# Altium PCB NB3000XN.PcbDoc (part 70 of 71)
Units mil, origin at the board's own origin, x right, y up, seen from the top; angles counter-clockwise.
Board outline 9527.56 x 6929.77 mil, 6 copper layers (Top Layer, GND+SHIELD, MidLayer1, MidLayer2, P2 - 3V3+5V0, Bottom Layer), stack 62.375 mil thick; 832 components, 1027 nets, 4655 pads, 4981 vias.
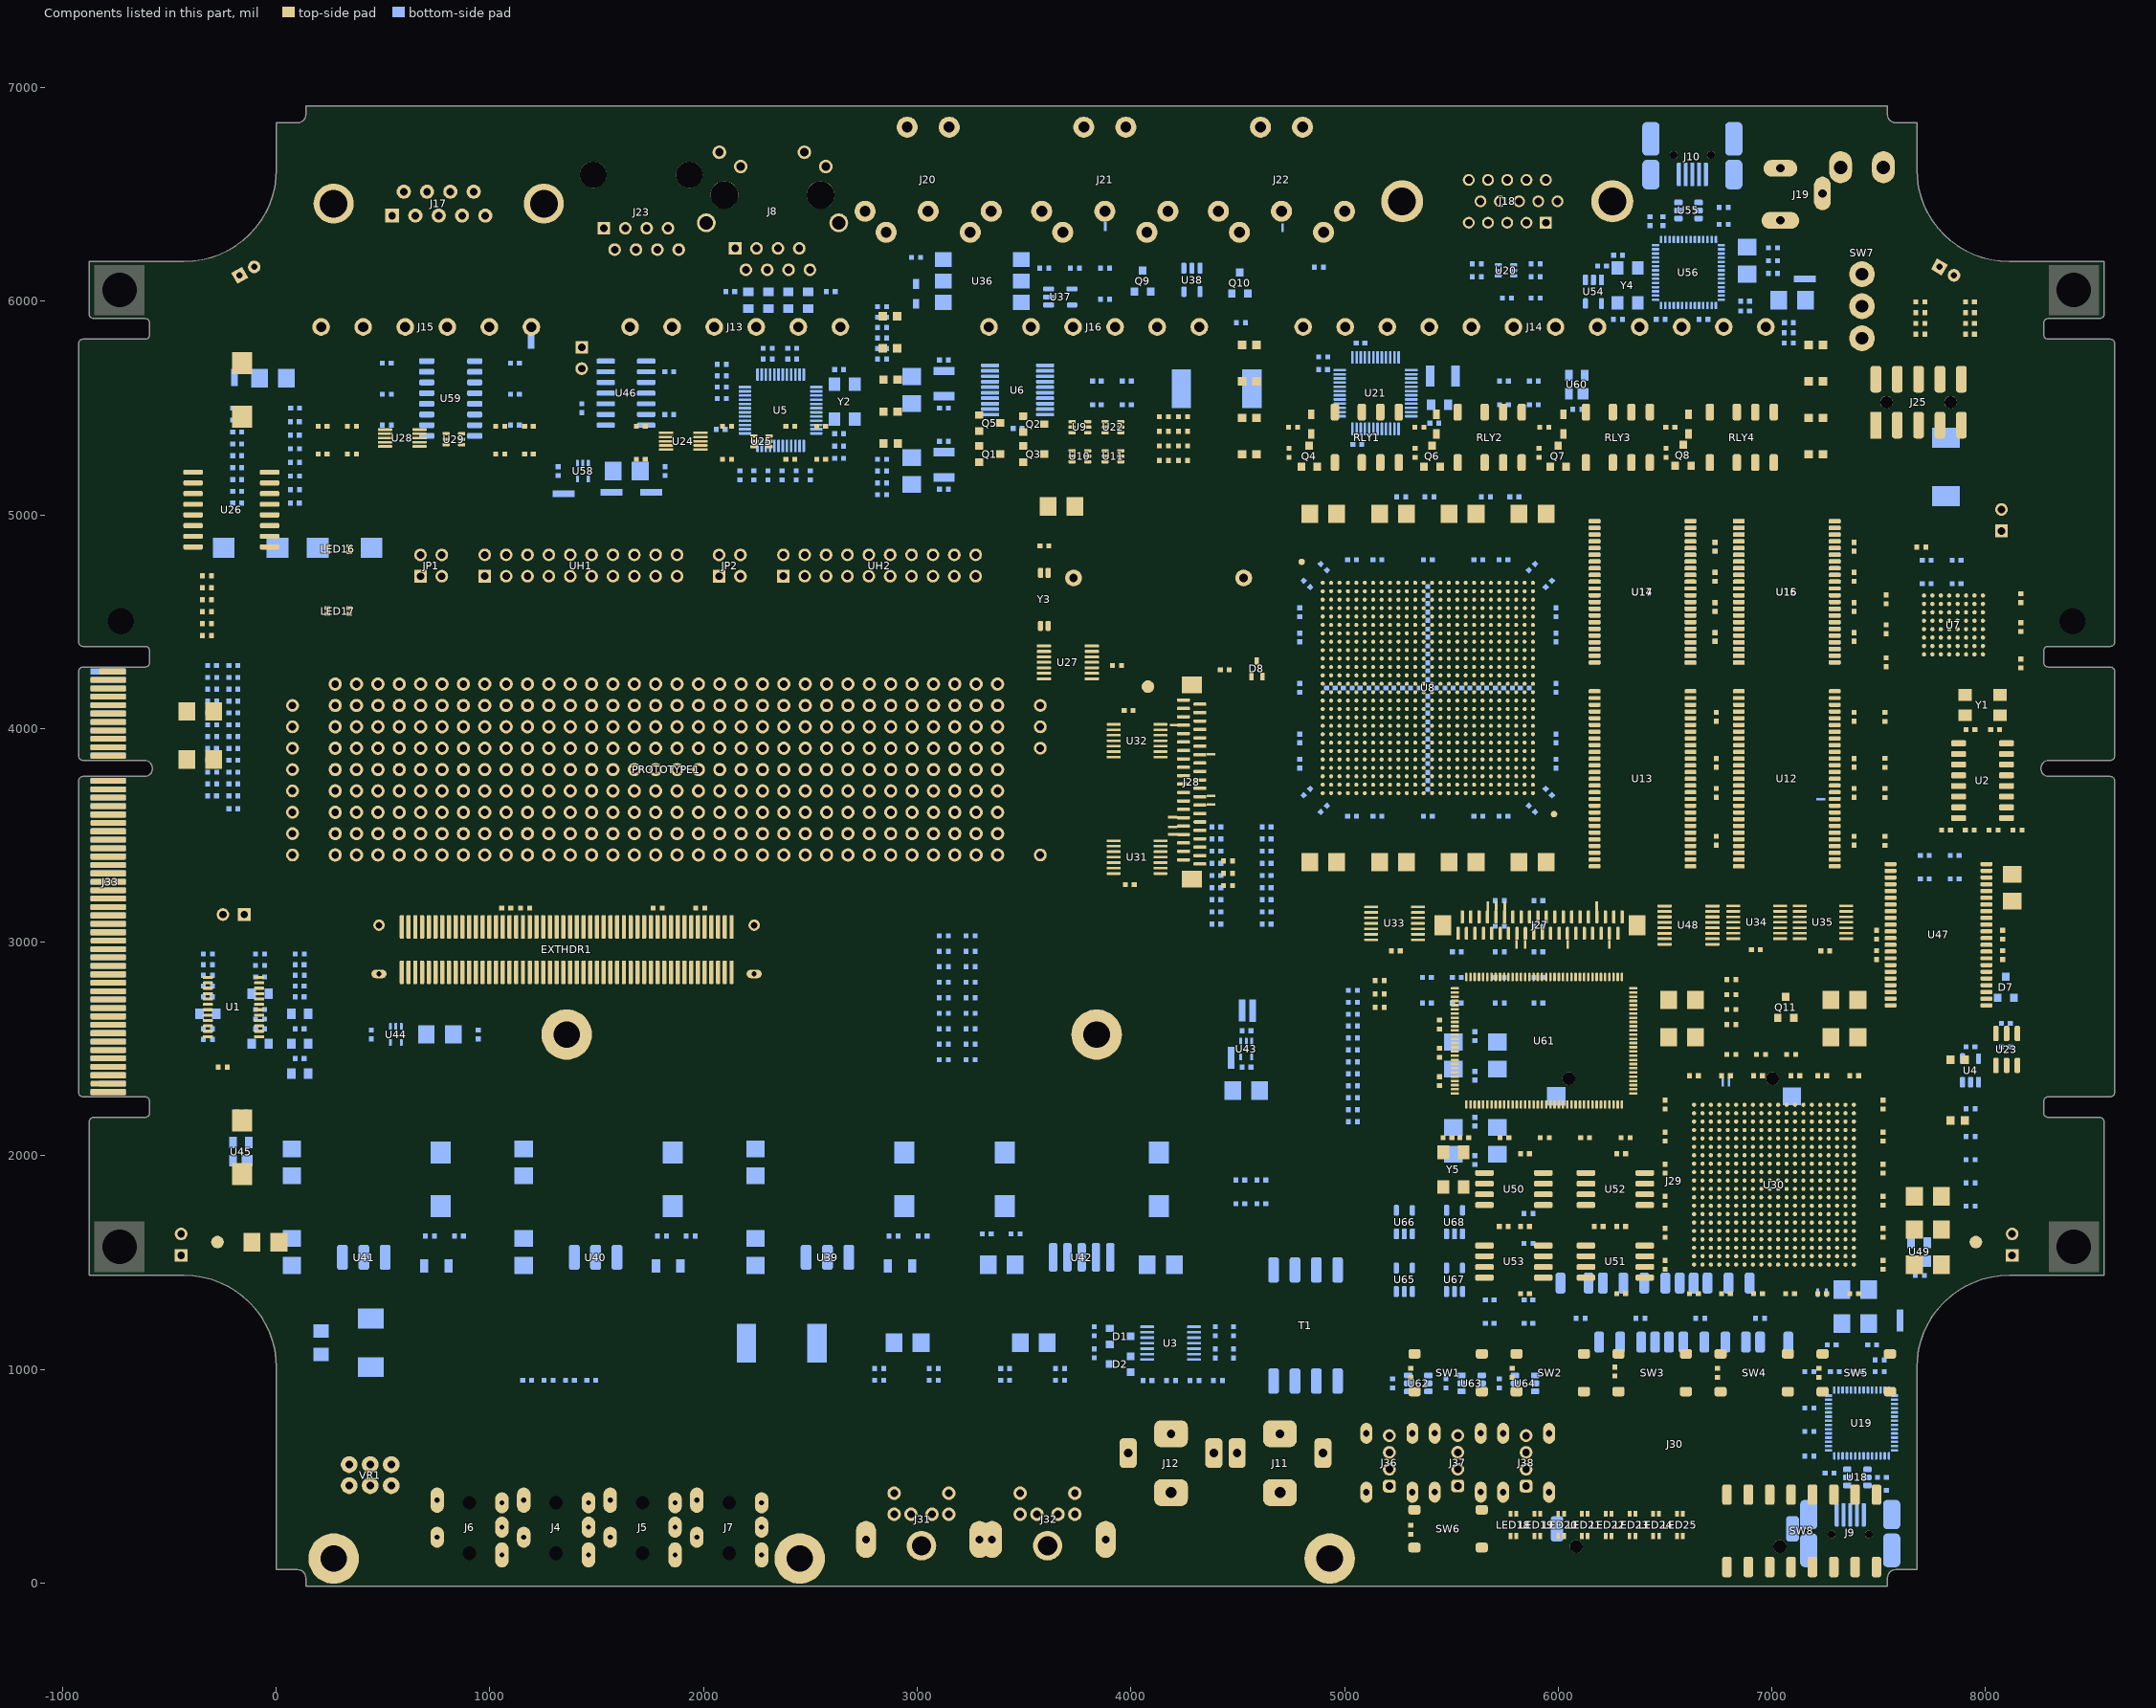
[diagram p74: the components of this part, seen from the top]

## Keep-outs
Keep-Out Layer:
  lines w15: -923.8,2295.89 -923.31,2291.51 -921.85,2287.35 -919.5,2283.62 -916.39,2280.5 -912.66,2278.15 -908.49,2276.7 -904.11,2276.2 -612.78,2276.2 -608.4,2275.71 -604.24,2274.25 -600.5,2271.91 -597.39,2268.79 -595.04,2265.06 -593.59,2260.9 -593.09,2256.52 -593.09,2199.42 -593.59,2195.04 -595.04,2190.88 -597.39,2187.15 -600.5,2184.03 -604.24,2181.68 -608.4,2180.23 -612.78,2179.74 -854.9,2179.74 -859.28,2179.24 -863.44,2177.79 -867.17,2175.44 -870.29,2172.32 -872.64,2168.59 -874.09,2164.43 -874.59,2160.05 -874.59,1441.32 -431.67,1441.32 -389.22,1439.23 -347.19,1433 -305.96,1422.67 -265.94,1408.35 -227.52,1390.18 -191.07,1368.33 -156.94,1343.01 -125.45,1314.46 -96.9,1282.97 -71.59,1248.83 -49.74,1212.37 -31.57,1173.95 -17.25,1133.93 -6.92,1092.7 -0.69,1050.65 1.4,1008.2 1.4,63.2 99.82,63.2 108.58,62.22 116.9,59.3 124.37,54.61 130.6,48.38 135.29,40.91 138.21,32.59 139.19,23.83 139.19,-15.55 7540.77,-15.55 7540.77,23.83 7541.76,32.59 7544.67,40.91 7549.36,48.38 7555.59,54.61 7563.06,59.31 7571.38,62.22 7580.14,63.2 7678.56,63.2 7678.56,1008.2 7680.65,1050.65 7686.89,1092.7 7697.21,1133.93 7711.53,1173.95 7729.7,1212.37 7751.55,1248.83 7776.87,1282.97 7805.41,1314.46 7836.9,1343.01 7871.03,1368.33 7907.49,1390.18 7945.91,1408.35 7985.92,1422.67 8027.15,1433 8069.19,1439.23 8111.63,1441.32 8554.55,1441.32 8554.55,2160.05 8554.05,2164.43 8552.6,2168.59 8550.25,2172.32 8547.13,2175.44 8543.4,2177.79 8539.24,2179.24 8534.86,2179.74 8292.74,2179.74 8288.36,2180.23 8284.2,2181.68 8280.47,2184.03 8277.35,2187.15 8275,2190.88 8273.55,2195.04 8273.05,2199.42 8273.05,2256.52 8273.55,2260.9 8275,2265.06 8277.35,2268.79 8280.47,2271.91 8284.2,2274.25 8288.36,2275.71 8292.74,2276.2 8584.08,2276.2 8588.46,2276.7 8592.62,2278.15 8596.35,2280.5 8599.46,2283.62 8601.81,2287.35 8603.27,2291.51 8603.76,2295.89 8603.76,3756.1 8603.27,3760.48 8601.81,3764.64 8599.46,3768.38 8596.35,3771.5 8592.62,3773.84 8588.46,3775.3 8584.08,3775.79 8296.67,3775.79 8288.9,3776.61 8281.46,3779.03 8274.69,3782.93 8268.88,3788.17 8264.28,3794.49 8261.1,3801.64 8259.48,3809.29 8259.48,3817.11 8261.1,3824.76 8264.28,3831.9 8268.88,3838.23 8274.69,3843.46 8281.46,3847.37 8288.9,3849.79 8296.67,3850.6 8584.08,3850.6 8588.46,3851.1 8592.62,3852.55 8596.35,3854.9 8599.46,3858.02 8601.81,3861.75 8603.27,3865.91 8603.76,3870.29 8603.76,4268.57 8603.27,4272.95 8601.81,4277.11 8599.46,4280.84 8596.35,4283.96 8592.62,4286.3 8588.46,4287.76 8584.08,4288.25 8292.74,4288.25 8288.36,4288.75 8284.2,4290.2 8280.47,4292.55 8277.35,4295.67 8275,4299.4 8273.55,4303.56 8273.05,4307.94 8273.05,4365.03 8273.55,4369.41 8275,4373.58 8277.35,4377.31 8280.47,4380.43 8284.2,4382.77 8288.36,4384.23 8292.74,4384.72 8584.08,4384.72 8588.46,4385.21 8592.62,4386.67 8596.35,4389.02 8599.46,4392.13 8601.81,4395.87 8603.27,4400.03 8603.76,4404.41 8603.76,5803 8603.27,5807.38 8601.81,5811.54 8599.46,5815.28 8596.35,5818.39 8592.62,5820.74 8588.46,5822.19 8584.08,5822.69 8292.74,5822.69 8288.36,5823.18 8284.2,5824.64 8280.47,5826.98 8277.35,5830.1 8275,5833.83 8273.55,5837.99 8273.05,5842.37 8273.05,5899.47 8273.55,5903.85 8275,5908.01 8277.35,5911.74 8280.47,5914.86 8284.2,5917.2 8288.36,5918.66 8292.74,5919.16 8534.86,5919.16 8539.24,5919.65 8543.4,5921.1 8547.13,5923.45 8550.25,5926.57 8552.6,5930.3 8554.05,5934.46 8554.55,5938.84 8554.55,6185.98 8110.73,6185.98 8068.37,6188.06 8026.42,6194.28 7985.28,6204.59 7945.35,6218.88 7907.01,6237.01 7870.63,6258.82 7836.57,6284.09 7805.14,6312.57 7776.66,6344 7751.4,6378.07 7729.59,6414.45 7711.46,6452.79 7697.17,6492.73 7686.87,6533.88 7680.65,6575.83 7678.56,6618.2 7678.56,6835.48 7580.14,6835.48 7571.38,6836.46 7563.05,6839.37 7555.59,6844.07 7549.36,6850.3 7544.67,6857.77 7541.76,6866.09 7540.77,6874.85 7540.77,6914.22 139.19,6914.22 139.19,6874.85 138.21,6866.09 135.29,6857.76 130.6,6850.3 124.37,6844.06 116.9,6839.37 108.58,6836.46 99.82,6835.47 1.4,6835.47 1.4,6618.2 -0.68,6575.83 -6.91,6533.87 -17.21,6492.73 -31.5,6452.79 -49.63,6414.45 -71.43,6378.07 -96.7,6344 -125.18,6312.57 -156.61,6284.09 -190.67,6258.82 -227.05,6237.01 -265.39,6218.88 -305.32,6204.59 -346.46,6194.28 -388.41,6188.06 -430.77,6185.98 -874.59,6185.98 -874.59,5938.84 -874.09,5934.46 -872.64,5930.3 -870.29,5926.57 -867.17,5923.45 -863.44,5921.1 -859.28,5919.65 -854.9,5919.15 -612.78,5919.15 -608.4,5918.66 -604.24,5917.2 -600.5,5914.86 -597.39,5911.74 -595.04,5908.01 -593.59,5903.85 -593.09,5899.47 -593.09,5842.37 -593.59,5837.99 -595.04,5833.83 -597.39,5830.1 -600.5,5826.98 -604.24,5824.64 -608.4,5823.18 -612.78,5822.69 -904.11,5822.69 -908.49,5822.19 -912.66,5820.74 -916.39,5818.39 -919.5,5815.27 -921.85,5811.54 -923.31,5807.38 -923.8,5803 -923.8,4404.41 -923.31,4400.03 -921.85,4395.87 -919.5,4392.13 -916.39,4389.02 -912.66,4386.67 -908.49,4385.21 -904.11,4384.72 -612.78,4384.72 -608.4,4384.23 -604.24,4382.77 -600.5,4380.43 -597.39,4377.31 -595.04,4373.58 -593.59,4369.41 -593.09,4365.03 -593.09,4307.94 -593.59,4303.56 -595.04,4299.4 -597.39,4295.67 -600.5,4292.55 -604.24,4290.2 -608.4,4288.75 -612.78,4288.25 -904.11,4288.25 -908.49,4287.76 -912.66,4286.3 -916.39,4283.96 -919.5,4280.84 -921.85,4277.11 -923.31,4272.95 -923.8,4268.56 -923.8,3870.29 -923.31,3865.91 -921.85,3861.75 -919.5,3858.01 -916.39,3854.9 -912.66,3852.55 -908.49,3851.1 -904.11,3850.6 -616.71,3850.6 -608.94,3849.79 -601.5,3847.37 -594.73,3843.46 -588.92,3838.23 -584.32,3831.9 -581.14,3824.76 -579.52,3817.11 -579.52,3809.29 -581.14,3801.64 -584.32,3794.49 -588.92,3788.17 -594.73,3782.93 -601.5,3779.02 -608.94,3776.61 -616.71,3775.79 -904.11,3775.79 -908.49,3775.3 -912.66,3773.84 -916.39,3771.49 -919.5,3768.38 -921.85,3764.64 -923.31,3760.48 -923.8,3756.1 -923.8,2295.89 ; -530.1,1864.15 -530.1,2218.52 -529.11,2227.28 -526.2,2235.6 -521.51,2243.07 -515.27,2249.3 -507.81,2253.99 -499.49,2256.91 -490.73,2257.89 -392.3,2257.89 -383.54,2256.91 -375.22,2253.99 -367.76,2249.3 -361.52,2243.07 -356.83,2235.6 -353.92,2227.28 -352.93,2218.52 -352.93,1864.15 -353.92,1855.38 -356.83,1847.06 -361.52,1839.6 -367.76,1833.36 -375.22,1828.67 -383.54,1825.76 -392.3,1824.77 -490.73,1824.77 -499.49,1825.76 -507.81,1828.67 -515.27,1833.36 -521.51,1839.6 -526.2,1847.06 -529.11,1855.38 -530.1,1864.15 ; -530.1,5407.88 -529.11,5399.11 -526.2,5390.79 -521.51,5383.32 -515.27,5377.09 -507.81,5372.4 -499.49,5369.49 -490.73,5368.5 -392.3,5368.5 -383.54,5369.49 -375.22,5372.4 -367.76,5377.09 -361.52,5383.32 -356.83,5390.79 -353.92,5399.11 -352.93,5407.88 -352.93,5762.25 -353.92,5771.01 -356.83,5779.33 -361.52,5786.8 -367.76,5793.03 -375.22,5797.72 -383.54,5800.64 -392.3,5801.62 -490.73,5801.62 -499.49,5800.64 -507.81,5797.72 -515.27,5793.03 -521.51,5786.8 -526.2,5779.33 -529.11,5771.01 -530.1,5762.25 -530.1,5407.88 ; 3623.45,3616.32 3624.43,3607.56 3627.34,3599.24 3632.03,3591.77 3638.27,3585.54 3645.73,3580.85 3654.05,3577.94 3662.81,3576.95 4017.15,3576.95 4025.91,3577.94 4034.23,3580.85 4041.69,3585.54 4047.93,3591.77 4052.62,3599.24 4055.53,3607.56 4056.52,3616.32 4056.52,3714.76 4055.53,3723.52 4052.62,3731.84 4047.93,3739.31 4041.69,3745.54 4034.23,3750.24 4025.91,3753.15 4017.15,3754.13 3662.81,3754.13 3654.05,3753.15 3645.73,3750.24 3638.27,3745.54 3632.03,3739.31 3627.34,3731.84 3624.43,3723.52 3623.45,3714.76 3623.45,3616.32 ; 4505.53,3715.21 4506.03,3710.83 4507.48,3706.67 4509.83,3702.94 4512.95,3699.82 4516.68,3697.47 4520.84,3696.02 4525.22,3695.52 4631.52,3695.52 4635.9,3696.02 4640.06,3697.47 4643.79,3699.82 4646.91,3702.94 4649.25,3706.67 4650.71,3710.83 4651.21,3715.21 4651.21,3912.08 4650.71,3916.47 4649.25,3920.63 4646.91,3924.36 4643.79,3927.48 4640.06,3929.82 4635.9,3931.28 4631.52,3931.77 4525.22,3931.77 4520.84,3931.28 4516.68,3929.82 4512.95,3927.48 4509.83,3924.36 4507.48,3920.63 4506.03,3916.47 4505.53,3912.08 4505.53,3715.21 ; 5224.07,2182.81 5224.57,2178.43 5226.02,2174.27 5228.37,2170.54 5231.48,2167.42 5235.21,2165.08 5239.37,2163.62 5243.76,2163.13 5350.06,2163.13 5354.43,2163.62 5358.6,2165.08 5362.33,2167.42 5365.45,2170.54 5367.79,2174.27 5369.25,2178.43 5369.74,2182.81 5369.74,2379.69 5369.25,2384.07 5367.79,2388.23 5365.45,2391.96 5362.33,2395.08 5358.6,2397.42 5354.43,2398.88 5350.06,2399.37 5243.76,2399.37 5239.37,2398.88 5235.21,2397.42 5231.48,2395.08 5228.37,2391.96 5226.02,2388.23 5224.57,2384.07 5224.07,2379.69 5224.07,2182.81 ; 7581.87,2182.81 7582.37,2178.43 7583.83,2174.27 7586.17,2170.54 7589.29,2167.42 7593.02,2165.08 7597.18,2163.62 7601.56,2163.13 7707.86,2163.13 7712.24,2163.62 7716.4,2165.08 7720.13,2167.42 7723.25,2170.54 7725.6,2174.27 7727.05,2178.43 7727.54,2182.81 7727.54,2379.69 7727.05,2384.07 7725.6,2388.23 7723.25,2391.96 7720.13,2395.08 7716.4,2397.42 7712.24,2398.88 7707.86,2399.37 7601.56,2399.37 7597.18,2398.88 7593.02,2397.42 7589.29,2395.08 7586.17,2391.96 7583.83,2388.23 7582.37,2384.07 7581.87,2379.69 7581.87,2182.81 ; 7603.95,3715.21 7604.45,3710.83 7605.9,3706.67 7608.25,3702.94 7611.37,3699.82 7615.1,3697.47 7619.26,3696.02 7623.64,3695.52 7729.94,3695.52 7734.32,3696.02 7738.48,3697.47 7742.21,3699.82 7745.33,3702.94 7747.67,3706.67 7749.13,3710.83 7749.62,3715.21 7749.62,3912.08 7749.13,3916.47 7747.67,3920.63 7745.33,3924.36 7742.21,3927.48 7738.48,3929.82 7734.32,3931.28 7729.94,3931.77 7623.64,3931.77 7619.26,3931.28 7615.1,3929.82 7611.37,3927.48 7608.25,3924.36 7605.9,3920.63 7604.45,3916.47 7603.95,3912.08 7603.95,3715.21 ; 8032.89,1864.15 8033.88,1855.39 8036.79,1847.06 8041.48,1839.6 8047.72,1833.36 8055.18,1828.67 8063.5,1825.76 8072.26,1824.77 8170.69,1824.77 8179.45,1825.76 8187.77,1828.67 8195.24,1833.36 8201.47,1839.6 8206.16,1847.06 8209.07,1855.39 8210.06,1864.15 8210.06,2218.52 8209.07,2227.28 8206.16,2235.6 8201.47,2243.07 8195.24,2249.3 8187.77,2254 8179.45,2256.91 8170.69,2257.89 8072.26,2257.89 8063.5,2256.91 8055.18,2254 8047.72,2249.3 8041.48,2243.07 8036.79,2235.6 8033.88,2227.28 8032.89,2218.52 8032.89,1864.15 ; 8032.89,5407.88 8033.88,5399.11 8036.79,5390.79 8041.48,5383.32 8047.72,5377.09 8055.18,5372.4 8063.5,5369.49 8072.26,5368.5 8170.69,5368.5 8179.45,5369.49 8187.77,5372.4 8195.24,5377.09 8201.47,5383.32 8206.16,5390.79 8209.07,5399.11 8210.06,5407.88 8210.06,5762.25 8209.07,5771.01 8206.16,5779.33 8201.47,5786.8 8195.24,5793.03 8187.77,5797.72 8179.45,5800.64 8170.69,5801.62 8072.26,5801.62 8063.5,5800.64 8055.18,5797.72 8047.72,5793.03 8041.48,5786.8 8036.79,5779.33 8033.88,5771.01 8032.89,5762.25 8032.89,5407.88

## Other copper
Top Layer:
  rectangle net GND: 3455,5210 3535,5285
  region net 2V5: 4114.02,1421.93 4114.02,1456.93 4039.02,1456.93 4039.02,1421.93
  region net 2V5: 4114.02,1525.79 4114.02,1560.79 4039.02,1560.79 4039.02,1525.79
  region net 2V5: 4167.01,1686.77 4167.01,1721.77 4092.01,1721.77 4092.01,1686.77
  region net 2V5: 4167.01,1808.82 4167.01,1843.82 4092.01,1843.82 4092.01,1808.82
  rectangle net GND: 3455,5350 3535,5439
  rectangle net GND: 3250,5355 3330,5430
  rectangle net GND: 3250,5210 3330,5285
  rectangle net GND: 115,4495 185,4525
  rectangle net 5V0: 5,1450 40,1525
  rectangle net 5V0: 108.86,1450 143.86,1525
  rectangle net GND: 108.86,1575.98 143.86,1650.98
  rectangle net 5V0: 258.86,1475 293.86,1585
  rectangle net 3V3: 428.86,1475 463.86,1670
  rectangle net 3V3: 454.85,1590 485,1670
  rectangle net GND: 5,1995 145,2070
  rectangle net 3V3: 5,1869.02 145,1944.02
  rectangle net 2V5: 1090,1868.03 1230,1943.03
  rectangle net GND: 1090,1994.02 1230,2069.02
  rectangle net 1V8: 2175,1868.03 2315,1943.03
  rectangle net GND: 2175,1994.02 2315,2069.02
  rectangle net 2V5: 1539.85,1590 1570,1670
  rectangle net 2V5: 1513.86,1475 1548.86,1670
  rectangle net 5V0: 1343.86,1475 1378.86,1585
  rectangle net 1V8: 2624.85,1590 2655,1670
  rectangle net 1V8: 2598.86,1475 2633.86,1670
  rectangle net 3V3: 2428.86,1475 2463.86,1585
  rectangle net GND: 2175,1574.02 2315,1649.02
  rectangle net 3V3: 2175,1448.03 2315,1523.03
  rectangle net 5V0: 648.86,1447.5 683.86,1522.5
  rectangle net 5V0: 704.68,1447.5 739.68,1522.5
  rectangle net GND: 763.03,1447.5 798.03,1522.5
  rectangle net GND: 818.86,1447.5 853.86,1522.5
  rectangle net GND: 1090,1575.98 1125,1650.98
  rectangle net 5V0: 1090,1450 1125,1525
  rectangle net GND: 1193.86,1575.98 1228.86,1650.98
  rectangle net 5V0: 1193.86,1450 1228.86,1525
  region net GND: 807.01,2060.79 807.01,2095.79 732.01,2095.79 732.01,2060.79
  region net GND: 807.01,1938.74 807.01,1973.74 732.01,1973.74 732.01,1938.74
  region net 3V3: 807.01,1808.82 807.01,1843.82 732.01,1843.82 732.01,1808.82
  region net 3V3: 807.01,1686.77 807.01,1721.77 732.01,1721.77 732.01,1686.77
  region net GND: 1892.01,2060.79 1892.01,2095.79 1817.01,2095.79 1817.01,2060.79
  region net GND: 1892.01,1938.74 1892.01,1973.74 1817.01,1973.74 1817.01,1938.74
  region net 2V5: 1862.01,1808.82 1862.01,1843.82 1787.01,1843.82 1787.01,1808.82
  region net 2V5: 1862.01,1686.77 1862.01,1721.77 1787.01,1721.77 1787.01,1686.77
  rectangle net 5V0: 1733.86,1447.5 1768.86,1522.5
  rectangle net 5V0: 1789.68,1447.5 1824.68,1522.5
  rectangle net GND: 1848.03,1447.5 1883.03,1522.5
  rectangle net GND: 1903.86,1447.5 1938.86,1522.5
  region net GND: 2977.01,2060.79 2977.01,2095.79 2902.01,2095.79 2902.01,2060.79
  region net GND: 3017.44,2052.64 2982.44,2052.64 2982.44,1977.64 3017.44,1977.64
  region net 1V8: 2895.39,1800.67 2860.39,1800.67 2860.39,1725.67 2895.39,1725.67
  region net 1V8: 2962.01,1686.77 2962.01,1721.77 2887.01,1721.77 2887.01,1686.77
  rectangle net 3V3: 2818.86,1447.5 2853.86,1522.5
  rectangle net 3V3: 2874.68,1447.5 2909.68,1522.5
  rectangle net GND: 2933.03,1447.5 2968.03,1522.5
  rectangle net GND: 2988.86,1447.5 3023.86,1522.5
  region net GND: 3446.46,2060.79 3446.46,2095.79 3371.46,2095.79 3371.46,2060.79
  region net GND: 3446.46,1938.74 3446.46,1973.74 3371.46,1973.74 3371.46,1938.74
  region net 1V2: 3364.84,1810.67 3329.84,1810.67 3329.84,1735.67 3364.84,1735.67
  region net 1V2: 3486.89,1810.67 3451.89,1810.67 3451.89,1735.67 3486.89,1735.67
  region net GND: 3369.02,1525.79 3369.02,1560.79 3294.02,1560.79 3294.02,1525.79
  region net 1V2: 3495,1525.79 3495,1560.79 3420,1560.79 3420,1525.79
  region net GND: 3369.02,1421.93 3369.02,1456.93 3294.02,1456.93 3294.02,1421.93
  region net 1V2: 3495,1421.93 3495,1456.93 3420,1456.93 3420,1421.93
  region net 1V2: 3680,1421.86 3680,1456.86 3540,1456.86 3540,1421.86
  rectangle net GND: 3753.86,1391.01 3788.86,1466.01
  region net GND: 4240,1421.93 4240,1456.93 4165,1456.93 4165,1421.93
  region net GND: 4240,1523.86 4240,1558.86 4165,1558.86 4165,1523.86
  region net GND: 4167.01,1938.74 4167.01,1973.74 4092.01,1973.74 4092.01,1938.74
  region net GND: 4167.01,2060.79 4167.01,2095.79 4092.01,2095.79 4092.01,2060.79
  region net 3V3: 386,1670 331,1670 331,1590 386,1590
  region net 3V3: 387.14,1670 363,1670 363,1475 387.14,1475
  region net 5V0: 357,1585 331,1585 331,1475 357,1475
  region net 5V0: 1442,1585 1416,1585 1416,1475 1442,1475
  region net 2V5: 1472.14,1670 1448,1670 1448,1475 1472.14,1475
  region net 2V5: 1471,1670 1416,1670 1416,1590 1471,1590
  region net 3V3: 2527,1585 2501,1585 2501,1475 2527,1475
  region net 1V8: 2557.14,1670 2533,1670 2533,1475 2557.14,1475
  region net 1V8: 2556,1670 2500.99,1670 2500.99,1590 2556,1590
  region net GND: 110.08,1648.78 110.08,1683.78 35.08,1683.78 35.08,1648.78
  region net 5V0: 757,3132 757,3155 670,3155 670,3132
  region net 3V3: 820,3131.84 820,3154.84 764.65,3154.84 764.65,3131.84
  region net 2V5: 882.84,3132 882.84,3155 827.48,3155 827.48,3132
  region net 1V8: 945.83,3132 945.83,3155 890.47,3155 890.47,3132
  region net PWMPWR: 3346,5718.96 3346,5741.96 3232.65,5741.96 3232.65,5718.96
  region net 5V0: 4707,5718 4707,5741.96 4622.65,5741.96 4622.65,5718
  rectangle net 5V0: -687.6,2292.5 -648.1,2345.8
  rectangle net +B: 7750,5265 7880,5315
  rectangle net GND: 7749.51,5134.9 7879.51,5184.9
  region net 1V2: 1008.98,3131.84 1008.98,3154.84 953.62,3154.84 953.62,3131.84
  rectangle net AUGND: 1095,560 1125,630
  pour cut-out: 4878.19,4701.81 5901.81,4701.81 5901.81,3678.19 4878.19,3678.19
  pour cut-out: 6615.37,2260.05 7403.7,2258.7 7403.7,1471.3 6616.3,1471.3
  pour cut-out: 7691.59,4643.83 8007.48,4642.48 8007.48,4327.52 7692.52,4327.52
MidLayer1:
  rectangle net SHIELD: 5590,364.61 5790,774.61
  rectangle net SHIELD: 3540,-15.55 3680,245
  rectangle net SHIELD: 2950,-15.55 3090,245
  rectangle net SHIELD: 3830,-15.55 3935,300
  rectangle net SHIELD: 3235,-15.55 3410,300
  rectangle net SHIELD: 5270,365 5470,775
MidLayer2:
  rectangle net SHIELD: 7470,6625 7575,6914.22
  rectangle net SHIELD: 7270,6625 7375,6914.22
  rectangle net SHIELD: 6160,6460 6350,6920
  rectangle net SHIELD: 5175,6460 5365,6920
Bottom Layer:
  drawing of 98 lines, arcs and shapes, not listed
P2 - 3V3+5V0 (plane layer: these items are gaps in the copper):
  lines w10: 0.1,500.1 2432.5,500.1 cw(c2432.5,467.5) 2465.1,467.5 ; 849.4,1356.3 986.3,1356.3 ccw(c986.3,1435.04) 1065.04,1435.04 1065.04,1510 cw(c1143.78,1510) 1143.78,1588.74 1210,1588.74 ccw(c1210,1648.74) 1252.43,1606.31 1293.55,1647.44 cw(c1335.98,1605.01) 1335.98,1665.01 1365,1665 cw(c1365,1586.26) 1443.74,1586.26 1443.74,1435.04 ccw(c1522.48,1435.04) 1522.48,1356.3 1618.7,1356.3 ccw(c1618.7,1435.04) 1697.44,1435.04 1697.44,1482.44 cw(c1776.18,1482.44) 1776.18,1561.18 cw(c1776.18,1482.44) 1854.92,1482.44 1854.92,1435.04 ccw(c1933.66,1435.04) 1933.66,1356.3 3703.7,1356.3 cw(c3703.7,1277.56) 3782.44,1277.56 3782.44,482.56 ccw(c3861.18,482.56) 3861.18,403.82 4950,403.82 ccw(c4950,482.56) 5028.74,482.56 5028.74,908.74 cw(c5107.48,908.74) 5107.48,987.48 5197.52,987.48 cw(c5197.52,908.74) 5276.26,908.74 ccw(c5331.94,908.74) 5331.94,853.06 5366.94,853.06 ccw(c5366.94,908.74) 5422.63,908.74 cw(c5478.31,908.74) 5478.31,964.43 cw(c5478.31,908.74) 5534,908.74 ccw(c5589.68,908.74) 5589.68,853.06 5616.94,853.06 ccw(c5616.94,908.74) 5672.63,908.74 cw(c5728.31,908.74) 5728.31,964.43 cw(c5728.31,908.74) 5784,908.74 ccw(c5839.68,908.74) 5839.68,853.06 6551.94,853.06 cw(c6551.94,774.32) 6630.68,774.32 6630.68,-14.86 ; 849.96,1356.3 cw(c849.96,1435.04) 771.22,1435.04 771.22,1490 ccw(c692.48,1490) 692.48,1568.74 ccw(c692.48,1490) 613.74,1490 613.74,1435.04 cw(c535,1435.04) 535,1356.3 438.7,1356.3 cw(c438.7,1435.04) 359.96,1435.04 359.96,1625.04 ccw(c281.22,1625.04) 281.22,1703.78 56.22,1703.78 cw(c56.22,1782.52) -22.52,1782.52 -22.52,2317.52 ccw(c-101.26,2317.52) -101.26,2396.26 -430,2396.26 cw(c-430,2475) -508.74,2475 -508.74,2863.78 cw(c-430,2863.78) -430,2942.52 302.52,2942.52 cw(c302.52,2863.78) 381.26,2863.78 381.26,2580 ccw(c460,2580) 460,2501.26 522.52,2501.26 ccw(c522.52,2580) 601.26,2580 601.26,2863.78 cw(c680,2863.78) 680,2942.52 ccw(c680,3021.26) 758.74,3021.26 758.74,3166.26 ccw(c680,3166.26) 680,3245 -430,3245 cw(c-430,3323.74) -508.74,3323.74 -508.74,3877.52 cw(c-430,3877.52) -430,3956.26 85.95,3956.26 ccw(c85.95,4035) 164.69,4035 164.69,4269.69 cw(c243.43,4269.69) 243.43,4348.43 651.61,4348.43 ccw(c651.61,4427.17) 730.35,4427.17 730.35,4832.17 cw(c809.09,4832.17) 809.09,4910.91 819.09,4910.91 cw(c819.09,4832.17) 897.83,4832.17 897.83,4427.17 ccw(c976.57,4427.17) 976.57,4348.43 3041.57,4348.43 cw(c3041.57,4269.69) 3120.31,4269.69 3120.31,3350.58 ccw(c3180.31,3350.58) 3137.89,3308.15 3505.46,2940.58 ccw(c3547.89,2983) 3547.89,2923 ; 1911.22,5183.63 1911.22,5621.22 cw(c1989.96,5621.22) 1989.96,5699.96 2695.08,5699.96 ccw(c2695.08,5778.7) 2773.82,5778.7 2773.82,5848.7 cw(c2852.56,5848.7) 2852.56,5927.44 cw(c2852.56,5848.7) 2931.3,5848.7 ccw(c3010.04,5848.7) 3010.04,5769.96 3565.04,5769.96 ccw(c3565.04,5848.7) 3643.78,5848.7 3643.78,5974.96 3643.78,6166.26 cw(c3722.52,6166.26) 3722.52,6245 cw(c3722.52,6166.26) 3801.26,6166.26 3801.26,5848.7 ccw(c3880,5848.7) 3880,5769.96 4152.56,5769.96 ccw(c4152.56,5848.7) 4231.3,5848.7 4231.3,6040 cw(c4310.04,6040) 4310.04,6118.74 4356.3,6118.74 cw(c4356.3,6040) 4435.04,6040 4435.04,5490 ccw(c4513.78,5490) 4513.78,5411.26 4560.04,5411.26 ccw(c4560.04,5490) 4638.78,5490 4638.78,5620 cw(c4717.52,5620) 4717.52,5698.74 cw(c4717.52,5620) 4796.26,5620 4796.26,5490 ccw(c4875,5490) 4875,5411.26 4921.26,5411.26 ccw(c4921.26,5490) 5000,5490 5000,5620 cw(c5078.74,5620) 5078.74,5698.74 5268.78,5698.74 cw(c5268.78,5620) 5347.52,5620 5347.52,5465 ccw(c5426.26,5465) 5426.26,5386.26 5541.22,5386.26 ccw(c5541.22,5465) 5619.96,5465 5619.96,5624.96 cw(c5698.7,5624.96) 5698.7,5703.7 6133.78,5703.7 cw(c6133.78,5624.96) 6212.52,5624.96 cw(c6133.78,5624.96) 6133.78,5546.22 6035,5546.22 ccw(c6035,5467.48) 5956.26,5467.48 ccw(c6035,5467.48) 6035,5388.74 6728.74,5388.74 ccw(c6728.74,5467.48) 6807.48,5467.48 6807.48,5752.52 ccw(c6728.74,5752.52) 6728.74,5831.26 6128.74,5831.26 cw(c6128.74,5910) 6050,5910 6050,6345 cw(c6152.5,6347.5) 6150,6450 6863.63,6450 cw(c6863.63,6394.32) 6919.32,6394.32 ; 1911.65,5183.21 ccw(c1971.65,5183.21) 1929.22,5140.78 2105.71,4964.29 cw(c2063.28,4921.87) 2123.28,4921.87 2123.28,4626.72 ccw(c2202.02,4626.72) 2202.02,4547.98 4307.02,4547.98 cw(c4307.02,4469.24) 4385.76,4469.24 4385.76,3279.24 ccw(c4464.5,3279.24) 4464.5,3200.5 5369.5,3195.88 ; 2465,-15 2465,465 ; 3547.91,2923.02 4223.78,2923.02 cw(c4223.78,2844.28) 4302.52,2844.28 4302.52,2690 ccw(c4381.26,2690) 4381.26,2611.26 4532.52,2611.26 ccw(c4532.52,2690) 4611.26,2690 4611.26,2844.28 cw(c4690,2844.28) 4690,2923.02 5028.7,2923.02 cw(c5028.7,2844.28) 5107.44,2844.28 5107.44,2077.56 ccw(c5186.18,2077.56) 5186.18,1998.82 5359.5,1998.82 ccw(c5359.5,2077.56) 5438.24,2077.56 cw(c5516.98,2077.56) 5516.98,2156.3 5656.22,2156.3 ccw(c5656.22,2235.04) 5734.96,2235.04 ccw(c5656.22,2235.04) 5656.22,2313.78 5516.98,2313.78 cw(c5516.98,2392.52) 5438.24,2392.52 5438.24,2402.52 ccw(c5359.5,2402.52) 5359.5,2481.26 cw(c5359.5,2560) 5280.76,2560 5280.76,2844.28 cw(c5359.5,2844.28) 5359.5,2923.02 ccw(c5359.5,3001.76) 5438.24,3001.76 5438.24,3121.76 ccw(c5359.5,3121.76) 5359.5,3200.5 ; 5015.76,4150.63 ccw(c4996.3,4150.63) 4976.84,4150.63 4920.63,4150.63 4920.63,4229.37 4976.84,4229.37 ccw(c4996.3,4229.37) 5015.76,4229.37 ; 5016.21,4150.63 cw(c5035.67,4150.63) 5055.13,4150.63 ; 5016.21,4229.37 ccw(c5035.67,4229.37) 5055.13,4229.37 ; 5055.58,4150.63 cw(c5075.04,4150.63) 5094.5,4150.63 ; 5055.58,4229.37 ccw(c5075.04,4229.37) 5094.5,4229.37 ; 5094.95,4150.63 cw(c5114.41,4150.63) 5133.87,4150.63 ; 5094.95,4229.37 ccw(c5114.41,4229.37) 5133.87,4229.37 ; 5134.32,4150.63 cw(c5153.78,4150.63) 5173.24,4150.63 ; 5134.32,4229.37 cw(c5153.78,4229.37) 5173.24,4229.37 ; 5173.69,4150.63 cw(c5193.15,4150.63) 5212.61,4150.63 ; 5173.69,4229.37 ccw(c5193.15,4229.37) 5212.61,4229.37 ; 5213.06,4150.63 cw(c5232.52,4150.63) 5251.98,4150.63 ; 5213.06,4229.37 ccw(c5232.52,4229.37) 5251.98,4229.37 5252.43,4229.82 5252.43,4308.11 cw(c5271.89,4308.11) 5271.89,4327.57 5350.18,4327.57 ; 5252.43,4150.18 5252.43,4071.89 ccw(c5271.89,4071.89) 5271.89,4052.43 5350.18,4052.43 ; 5350.63,3815.76 cw(c5350.63,3796.3) 5350.63,3776.84 5350.63,3720.63 5429.37,3720.63 5429.37,3776.84 cw(c5429.37,3796.3) 5429.37,3815.76 ; 5350.63,3816.21 ccw(c5350.63,3835.67) 5350.63,3855.13 ; 5350.63,3855.58 ccw(c5350.63,3875.04) 5350.63,3894.5 ; 5350.63,3894.95 ccw(c5350.63,3914.41) 5350.63,3933.87 ; 5350.63,3934.32 ccw(c5350.63,3953.78) 5350.63,3973.24 ; 5350.63,3973.69 ccw(c5350.63,3993.15) 5350.63,4012.61 ; 5350.63,4013.06 cw(c5350.63,4032.52) 5350.63,4051.98 ; 5350.63,4328.02 ccw(c5350.63,4347.48) 5350.63,4366.94 ; 5350.63,4367.39 ccw(c5350.63,4386.85) 5350.63,4406.31 ; 5350.63,4406.76 ccw(c5350.63,4426.22) 5350.63,4445.68 ; 5350.63,4446.13 ccw(c5350.63,4465.59) 5350.63,4485.05 ; 5350.63,4485.5 ccw(c5350.63,4504.96) 5350.63,4524.42 ; 5350.63,4524.87 ccw(c5350.63,4544.33) 5350.63,4563.79 ; 5350.63,4564.24 ccw(c5350.63,4583.7) 5350.63,4603.16 5350.63,4659.37 5429.37,4659.37 5429.37,4603.16 ccw(c5429.37,4583.7) 5429.37,4564.24 ; 5429.37,3816.21 cw(c5429.37,3835.67) 5429.37,3855.13 ; 5429.37,3855.58 cw(c5429.37,3875.04) 5429.37,3894.5 ; 5429.37,3894.95 cw(c5429.37,3914.41) 5429.37,3933.87 ; 5429.37,3934.32 ccw(c5429.37,3953.78) 5429.37,3973.24 ; 5429.37,3973.69 cw(c5429.37,3993.15) 5429.37,4012.61 ; 5429.37,4013.06 cw(c5429.37,4032.52) 5429.37,4051.98 ; 5429.37,4328.02 cw(c5429.37,4347.48) 5429.37,4366.94 ; 5429.37,4367.39 cw(c5429.37,4386.85) 5429.37,4406.31 ; 5429.37,4406.76 ccw(c5429.37,4426.22) 5429.37,4445.68 ; 5429.37,4446.13 cw(c5429.37,4465.59) 5429.37,4485.05 ; 5429.37,4485.5 cw(c5429.37,4504.96) 5429.37,4524.42 ; 5429.37,4524.87 cw(c5429.37,4544.33) 5429.37,4563.79 ; 5429.82,4052.43 5508.11,4052.43 ccw(c5508.11,4071.89) 5527.57,4071.89 5527.57,4150.18 ; 5429.82,4327.57 5508.11,4327.57 cw(c5508.11,4308.11) 5527.57,4308.11 5527.57,4229.82 ; 5528.02,4150.63 cw(c5547.48,4150.63) 5566.94,4150.63 ; 5528.02,4229.37 ccw(c5547.48,4229.37) 5566.94,4229.37 ; 5567.39,4150.63 cw(c5586.85,4150.63) 5606.31,4150.63 ; 5567.39,4229.37 ccw(c5586.85,4229.37) 5606.31,4229.37 ; 5606.76,4150.63 ccw(c5626.22,4150.63) 5645.68,4150.63 ; 5606.76,4229.37 ccw(c5626.22,4229.37) 5645.68,4229.37 ; 5646.13,4150.63 cw(c5665.59,4150.63) 5685.05,4150.63 ; 5646.13,4229.37 ccw(c5665.59,4229.37) 5685.05,4229.37 ; 5685.5,4150.63 cw(c5704.96,4150.63) 5724.42,4150.63 ; 5685.5,4229.37 ccw(c5704.96,4229.37) 5724.42,4229.37 ; 5724.87,4150.63 cw(c5744.33,4150.63) 5763.79,4150.63 ; 5724.87,4229.37 ccw(c5744.33,4229.37) 5763.79,4229.37 ; 5764.24,4150.63 cw(c5783.7,4150.63) 5803.16,4150.63 5859.37,4150.63 5859.37,4229.37 5803.16,4229.37 cw(c5783.7,4229.37) 5764.24,4229.37 ; 6814.15,1924.28 cw(c6814.15,1943.74) 6814.15,1963.2 ; 6814.61,1962.74 6852.52,1962.74 ; 6814.65,1923.76 cw(c6814.65,1905.04) 6833.38,1905.04 ; 6833.52,1905 6833.52,1786.26 ccw(c6852.52,1786.26) 6852.52,1767.26 ; 6853.19,1767.12 cw(c6853.19,1748.39) 6871.91,1748.39 ; 6853.19,1962.88 ccw(c6853.19,1981.61) 6871.91,1981.61 ; 6872.43,1747.89 ccw(c6891.89,1747.89) 6911.35,1747.89 ; 6872.43,1982.11 cw(c6891.89,1982.11) 6911.35,1982.11 ; 6911.87,1748.39 cw(c6930.59,1748.39) 6930.59,1767.12 7089.41,1767.12 cw(c7089.41,1748.39) 7108.13,1748.39 ; 6911.87,1981.61 ccw(c6930.59,1981.61) 6930.59,1962.88 7089.41,1962.88 ccw(c7089.41,1981.61) 7108.13,1981.61 ; 7108.65,1747.89 ccw(c7128.11,1747.89) 7147.57,1747.89 ; 7108.65,1982.11 cw(c7128.11,1982.11) 7147.57,1982.11 ; 7148.09,1748.39 cw(c7166.81,1748.39) 7166.81,1767.12 ; 7148.09,1981.61 ccw(c7166.81,1981.61) 7166.81,1962.88 ; 7167.48,1767.26 ccw(c7167.48,1786.26) 7186.48,1786.26 7186.48,1943.74 ccw(c7167.48,1943.74) 7167.48,1962.74 ; 8603.29,3084.53 8200.47,3084.53 7457.48,3084.53 ccw(c7457.48,3028.84) 7401.8,3028.84 7401.8,2931.8 cw(c7346.11,2931.8) 7346.11,2876.11 6930,2876.11 cw(c6930,2931.8) 6874.32,2931.8 6874.32,2999.32 cw(c6930,2999.32) 6930,3055 ccw(c6930,3110.68) 6985.68,3110.68 6985.68,3183.2 cw(c7041.37,3183.2) 7041.37,3238.89 7346.11,3238.89 cw(c7346.11,3183.2) 7401.8,3183.2 ccw(c7457.48,3183.2) 7457.48,3127.52 8100,3127.52 ccw(c8100,3206.26) 8178.74,3206.26 8178.74,4245.04 8178.74,5140.04 ccw(c8100,5140.04) 8100,5218.78 7981.22,5218.78 cw(c7981.22,5297.52) 7902.48,5297.52 ; 6919.32,6394.32 cw(c6975,6394.32) 6975,6450 7045,6450 cw(c7042.5,6192.5) 7300,6190 7300,5980 ccw(c7378.74,5980) 7378.74,5901.26 7823.74,5901.26 cw(c7823.74,5822.52) 7902.48,5822.52 7902.48,5297.52 ; 6919.32,6394.32 6919.32,6362.94 ccw(c6975,6362.94) 6975,6307.26 7010,6307.26 cw(c7010,6251.57) 7065.68,6251.57 7065.68,6204.32 ccw(c7121.37,6204.32) 7121.37,6148.63 7161.37,6148.63 cw(c7161.37,6092.95) 7217.05,6092.95 7217.05,5790 ccw(c7295.79,5790) 7295.79,5711.26 7471.94,5711.26 7663.74,5711.26 cw(c7663.74,5647.68) 7727.32,5647.68 7727.32,5297.52 ccw(c7806.06,5297.52) 7806.06,5218.78 7823.74,5218.78 ccw(c7823.74,5297.52) 7902.48,5297.52
  text "5V0" at 7345,6299 h30
  text "+B" at 7160,6245 h30
  text "3V3" at 6955,6150 h30
  text "AUGND" at 75,430 h30
GND+SHIELD (plane layer: these items are gaps in the copper):
  lines w10: -530.1,1895 -530.1,1565 ccw(c-470.1,1565) -470.1,1505 515,1505 cw(c515,1445) 575,1445 575,1210 cw(c515,1210) 515,1150 210,1150 ccw(c210,1090) 150,1090 150,375 ccw(c210,375) 210,315 2775,315 ; -526.2,2235.6 -526.2,5396.2 ; -525.94,3175.26 79.74,3175.26 ccw(c79.74,3205.26) 109.74,3205.26 109.75,4033.54 ccw(c76.12,4033.54) 76.12,4067.16 cw(c76.12,4108.23) 76.12,4149.31 ccw(c76.12,4182.93) 109.75,4182.93 109.74,5475 109.74,5739.74 ccw(c79.74,5739.74) 79.74,5769.74 -325.77,5769.74 ; -430,2270 -430,2975 cw(c-400,2975) -400,3005 195,3005 cw(c195,2975) 225,2975 225,2260 cw(c195,2260) 195,2230 -340,2230 ; -352.91,5741.94 181.84,6276.69 cw(c224.27,6234.27) 224.27,6294.27 365.43,6294.27 ccw(c365.43,6354.27) 425.43,6354.27 425.43,6565.73 cw(c485.43,6565.73) 485.43,6625.73 1035.73,6625.73 cw(c1035.73,6565.73) 1095.73,6565.73 1095.73,6354.27 ccw(c1155.73,6354.27) 1155.73,6294.27 1391.56,6294.27 ccw(c1391.56,6354.27) 1433.99,6311.84 1534.57,6412.43 cw(c1577,6370) 1577,6430 1791,6430 cw(c1791,6370) 1833.43,6412.43 1934.01,6311.84 ccw(c1976.44,6354.27) 1976.44,6294.27 ; 822.49,2662.37 822.49,3217.66 ccw(c762.49,3217.66) 804.91,3260.09 752.66,3312.34 cw(c795.09,3354.77) 735.09,3354.77 735.05,3408.23 cw(c776.12,3408.23) 817.19,3408.23 817.23,3354.77 ccw(c877.23,3354.77) 834.81,3312.34 ; 822.85,2662.01 ccw(c882.85,2662.01) 840.42,2619.58 1247.57,2212.43 cw(c1205.15,2170) 1265.15,2170 ; 834.94,3312.34 869.85,3277.43 cw(c827.43,3235) 887.43,3235 ; 887.43,2887.57 1632.57,2887.57 cw(c1632.57,2827.57) 1675,2870 2332.57,2212.43 cw(c2290.15,2170) 2350.15,2170 ; 887.43,3167.57 1000,3167.57 ; 887.43,3234.99 887.43,2702.42 ccw(c947.43,2702.42) 905.01,2660 ; 905.15,2660 1332.57,2232.57 ccw(c1375,2275) 1375,2215 1695.69,2215 cw(c1695.69,2155) 1755.69,2155 1755.69,1915 ccw(c1815.69,1915) 1815.69,1855 cw(c1815.69,1795) 1875.69,1795 1875.69,1674.02 cw(c1815.69,1674.02) 1815.69,1614.02 1605,1614.02 ccw(c1605,1554.02) 1545,1554.02 1545,1480 ; 950,3165 950,3035 ccw(c1010,3035) 1010,2975 1730,2975 cw(c1730,2915) 1772.43,2957.43 2978.26,1751.59 ccw(c3020.69,1794.02) 3020.69,1734.02 ; 952.57,3167.57 982.57,3167.57 1737.09,3167.57 cw(c1737.09,3107.57) 1779.52,3150 3027.57,1901.94 ccw(c3070,1944.37) 3070,1884.37 3359.37,1884.37 4834.69,1884.37 ccw(c4834.69,1963.11) 4913.43,1963.11 4913.43,2046.57 4913.43,2752.52 cw(c4992.17,2752.52) 4992.17,2831.26 5081.26,2831.26 ccw(c5081.26,2910) 5160,2910 5160,3490 cw(c5238.74,3490) 5238.74,3568.74 ccw(c5238.74,3647.48) 5317.48,3647.48 5317.48,3920 ccw(c5238.74,3920) 5294.42,3975.68 cw(c5350.1,4031.36) 5271.36,4031.36 5271.89,4053.98 cw(c5271.89,4071.89) 5271.89,4089.8 ; 1214,5562.61 1214,5789.88 ccw(c1184,5789.88) 1184,5819.88 cw(c1184,5849.88) 1154,5849.88 1154,5905.73 cw(c1184,5905.73) 1184,5935.73 1264.78,5935.73 cw(c1264.78,5905.73) 1294.78,5905.73 1294.78,5502.61 1294.78,5227.39 cw(c1264.78,5227.39) 1264.78,5197.39 139.74,5197.39 cw(c139.74,5227.39) 109.74,5227.39 109.74,5502.61 cw(c139.74,5502.61) 139.74,5532.61 1184,5532.61 ccw(c1184,5562.61) 1214,5562.61 ; 1265,2169.85 1265,2005 cw(c1215,2005) 1215,1955 1095,1955 ccw(c1095,1905) 1045,1905 ccw(c1095,1905) 1095,1855 1385,1855 cw(c1385,1795) 1445,1795 1445,1480 ; 1445,1515 1445,1300 ccw(c1495,1300) 1495,1250 4075,1250 ; 1545,1515 1545,1390 ccw(c1595,1390) 1595,1340 3975,1340 ; 1978.67,6294.27 2053.67,6294.27 2602.33,6294.27 2677.33,6294.27 ; 2350,2169.85 2350,2005 cw(c2300,2005) 2300,1955 2180,1955 ccw(c2180,1905) 2130,1905 ccw(c2180,1905) 2180,1855 2470,1855 cw(c2470,1795) 2530,1795 2530,1480 ccw(c2580,1480) 2580,1430 ccw(c2580,1480) 2630,1480 2630,1554.02 cw(c2690,1554.02) 2690,1614.02 2900.69,1614.02 ccw(c2900.69,1674.02) 2960.69,1674.02 cw(c3020.69,1674.02) 3020.69,1734.02 ; 2630.08,5532.61 ccw(c2630.08,5562.61) 2660.08,5562.61 2660.08,5789.88 ccw(c2630.08,5789.88) 2630.08,5819.88 cw(c2630.08,5849.88) 2600.08,5849.88 2600.08,5905.73 cw(c2630.08,5905.73) 2630.08,5935.73 2710.87,5935.73 cw(c2710.87,5905.73) 2740.87,5905.73 2740.87,5502.61 2740.87,5227.39 cw(c2710.87,5227.39) 2710.87,5197.39 1585.83,5197.39 cw(c1585.83,5227.39) 1555.83,5227.39 1555.83,5502.61 cw(c1585.83,5502.61) 1585.83,5532.61 2635,5532.61 ; 2679.56,6294.27 ccw(c2679.56,6354.27) 2721.99,6311.84 2976.84,6566.69 cw(c3019.27,6524.27) 3019.27,6584.27 4952.17,6584.27 cw(c4952.17,6524.27) 4994.6,6566.69 5188.72,6372.57 ccw(c5231.14,6415) 5231.14,6355 5306.14,6355 ; 2775.11,315.04 cw(c2775.11,255.04) 2817.54,297.46 2837.45,277.55 ccw(c2879.87,319.98) 2879.87,259.98 3172.33,259.98 ccw(c3172.33,319.98) 3214.76,277.55 3234.67,297.46 cw(c3277.09,255.04) 3277.09,315.04 3365.11,315.04 cw(c3365.11,255.04) 3407.54,297.46 3427.45,277.55 ccw(c3469.87,319.98) 3469.87,259.98 3762.33,259.98 ccw(c3762.33,319.98) 3804.76,277.55 3824.67,297.46 cw(c3867.09,255.04) 3867.09,315.04 3896.61,315.04 cw(c3896.61,255.04) 3939.03,297.46 3958.94,277.55 ccw(c4001.37,319.98) 4001.37,259.98 4990,259.98 ccw(c4990,319.98) 5050,319.98 5050,750 cw(c5080,750) 5080,780 5104.44,780 cw(c5104.44,750) 5134.44,750 5134.44,405 ccw(c5164.44,405) 5164.44,375 5235.35,375 5895.35,375 ccw(c5895.35,405) 5925.35,405 5925.35,750 cw(c5955.35,750) 5955.35,780 5979.79,780 cw(c5979.79,750) 6009.79,750 6009.79,319.98 cw(c5979.79,319.98) 5979.79,289.98 5359.98,289.98 ccw(c5359.98,259.98) 5329.98,259.98 5329.98,164.98 ccw(c5359.98,164.98) 5359.98,134.98 6590.02,134.98 cw(c6590.02,74.98) 6632.45,117.41 6652.35,97.5 ccw(c6694.78,139.93) 6694.78,79.93 7089.93,79.93 ccw(c7089.93,109.93) 7119.93,109.93 7119.93,354.93 cw(c7149.93,354.93) 7149.93,384.93 7225,384.93 cw(c7225,354.93) 7255,354.93 7255,295 ccw(c7285,295) 7285,265 7429.01,265 ccw(c7429.01,295) 7459.01,295 7459.01,354.93 cw(c7489.01,354.93) 7489.01,384.93 7564.09,384.93 cw(c7564.09,354.93) 7594.09,354.93 7594.09,64.12 ; 3975,1339.96 ccw(c3975,1389.96) 4025,1389.96 4025,1524.96 cw(c4075,1524.96) 4075,1574.96 cw(c4075,1524.96) 4125,1524.96 4125,1299.96 cw(c4075,1299.96) 4075,1249.96 ; 5160,4920 5160,5000 cw(c5238.74,5000) 5238.74,5078.74 5541.26,5078.74 cw(c5541.26,5000) 5620,5000 5620,4925 cw(c5541.26,4925) 5541.26,4846.26 ccw(c5541.26,4767.52) 5462.52,4767.52 5462.52,4460 ccw(c5541.26,4460) 5485.58,4404.32 cw(c5429.9,4348.64) 5508.64,4348.64 5507.58,4326.19 cw(c5507.58,4308.27) 5525.49,4308.2 ; 5160,4925 ccw(c5238.74,4925) 5238.74,4846.26 cw(c5238.74,4767.52) 5317.48,4767.52 5317.48,4460 cw(c5238.74,4460) 5294.42,4404.32 ccw(c5350.1,4348.64) 5271.36,4348.64 5271.89,4329.51 ; 5233.37,6355 5308.37,6355 ccw(c5308.37,6415) 5350.8,6372.57 5605.65,6627.43 ; 5271.36,4247.12 cw(c5271.36,4229.21) 5271.36,4211.29 5272.42,4168.71 ccw(c5272.42,4150.79) 5272.42,4132.88 ; 5271.36,4290.03 ccw(c5271.36,4307.95) 5271.36,4325.86 ; 5271.89,4089.86 ccw(c5271.89,4111.26) 5271.89,4132.66 ; 5271.89,4247.34 cw(c5271.89,4268.74) 5271.89,4290.14 ; 5508.11,4032.52 5508.64,4054.14 cw(c5508.64,4072.05) 5508.64,4089.97 ; 5508.11,4089.86 ccw(c5508.11,4111.26) 5508.11,4132.66 ; 5508.64,4031.36 cw(c5429.9,4031.36) 5485.58,3975.68 ccw(c5541.26,3920) 5462.52,3920 5462.52,3647.48 ccw(c5541.26,3647.48) 5541.26,3568.74 cw(c5541.26,3490) 5620,3490 5620,3260 cw(c5541.26,3260) 5541.26,3181.26 ccw(c5541.26,3102.52) 5462.52,3102.52 5462.52,2742.48 cw(c5383.78,2742.48) 5383.78,2663.74 5294.68,2663.74 ccw(c5294.68,2585) 5215.94,2585 5215.94,2460.94 5215.94,1963.43 ccw(c5294.68,1963.43) 5294.68,1884.68 6793.46,1884.68 ccw(c6793.46,1963.43) 6872.2,1963.43 6872.2,2561.57 ccw(c6793.46,2561.57) 6793.46,2640.32 6650,2640.32 cw(c6650,2719.06) 6571.26,2719.06 cw(c6650,2719.06) 6650,2797.8 7370,2797.8 cw(c7370,2719.06) 7448.74,2719.06 cw(c7370,2719.06) 7370,2640.32 7187.17,2640.32 ccw(c7187.17,2561.57) 7108.43,2561.57 7108.43,1963.43 ccw(c7187.17,1963.43) 7187.17,1884.68 7475,1884.68 7680.32,1884.68 cw(c7680.32,1825.63) 7680.32,1766.57 7475,1766.57 7187.17,1766.57 ccw(c7187.17,1687.83) 7108.43,1687.83 7108.42,1400 cw(c7029.68,1400) 7029.68,1321.26 6950.95,1321.26 cw(c6950.95,1400) 6872.21,1400 6872.2,1687.83 ccw(c6793.46,1687.83) 6793.46,1766.57 3825.94,1766.57 ccw(c3825.94,1687.83) 3747.2,1687.83 3747.2,1497.8 cw(c3668.46,1497.8) 3668.46,1419.06 3470,1419.06 cw(c3470,1497.8) 3391.26,1497.8 cw(c3470,1497.8) 3470,1576.54 ccw(c3470,1655.28) 3548.74,1655.28 ccw(c3470,1655.28) 3470,1734.02 3020.69,1734.02 ; 5508.64,4132.88 cw(c5508.64,4150.79) 5508.64,4168.71 5507.58,4211.29 ccw(c5507.58,4229.21) 5525.49,4229.28 ; 5525.1,4229.46 cw(c5543.01,4229.53) 5543.01,4247.45 ; 5525.1,4308.02 ccw(c5543.01,4307.95) 5543.01,4290.03 ; 5542.66,4247.34 5547.48,4247.34 ccw(c5547.48,4268.74) 5547.48,4290.14 5542.66,4290.14 ; 5605.94,6627.43 cw(c5648.37,6585) 5648.37,6645 5875,6645 cw(c5875,6585) 5917.43,6627.43 ; 5917.72,6627.43 6172.57,6372.57 ccw(c6215,6415) 6215,6355 6290,6355 ccw(c6290,6415) 6332.43,6372.57 6449.85,6490 cw(c6492.28,6447.57) 6492.28,6507.57 6495.99,6507.57 ccw(c6495.99,6537.57) 6525.99,6537.57 6525.99,6619 cw(c6555.99,6619) 6555.99,6649 6700,6649 cw(c6700,6619) 6730,6619 6730,6559.07 ccw(c6760,6559.07) 6760,6529.07 6860,6529.07 ccw(c6860,6589.07) 6920,6589.07 6920,6615 cw(c6980,6615) 6980,6675 7145,6675 cw(c7145,6615) 7187.43,6657.43 7336.57,6508.41 ccw(c7379,6550.84) 7379,6490.84 7697.85,6490.84
  text "AUGND" at -310,5725 h30
  text "AGND" at 155,5470 h30
  text "AGND" at 1601.08,5470 h30
  text "AUGND" at -410,2965 h30
  text "GND" at 1795,2365 h30
  text "2V5" at 1515,1950 h30
  text "1V8" at 2620,1900 h30
  text "1V2" at 3600,1775 h30
  text "SHIELD" at 75,1335 h30
Multi-Layer:
  pour cut-out: -701.84,4350 -1000,4350 -1000,2240 -701.84,2240
  lines w15 net SHIELD: -923.8,4404.41 -923.8,5803 -923.31,5807.38 -921.85,5811.54 -919.5,5815.27 -916.39,5818.39 -912.66,5820.74 -908.49,5822.19 -904.11,5822.69 -612.78,5822.69 -608.4,5823.18 -604.24,5824.64 -600.5,5826.98 -597.39,5830.1 -595.04,5833.83 -593.59,5837.99 -593.09,5842.37 -593.09,5899.47 -593.59,5903.85 -595.04,5908.01 -597.39,5911.74 -600.5,5914.86 -604.24,5917.2 -608.4,5918.66 -612.78,5919.15 -854.9,5919.15 -859.28,5919.65 -863.44,5921.1 -867.17,5923.45 -870.29,5926.57 -872.64,5930.3 -874.09,5934.46 -874.59,5938.84 -874.59,6185.98 -430.77,6185.98 -388.41,6188.06 -346.46,6194.28 -305.32,6204.59 -265.39,6218.88 -227.05,6237.01 -190.67,6258.82 -156.61,6284.09 -125.18,6312.57 -96.7,6344 -71.43,6378.07 -49.63,6414.45 -31.5,6452.79 -17.21,6492.73 -6.91,6533.87 -0.68,6575.83 1.4,6618.2 1.4,6835.47 99.82,6835.47 108.58,6836.46 116.9,6839.37 124.37,6844.06 130.6,6850.3 135.29,6857.76 138.21,6866.09 139.19,6874.85 139.19,6914.22 7540.77,6914.22 7540.77,6874.85 7541.76,6866.09 7544.67,6857.77 7549.36,6850.3 7555.59,6844.07 7563.05,6839.37 7571.38,6836.46 7580.14,6835.48 7678.56,6835.48 7678.56,6618.2 7680.65,6575.83 7686.87,6533.88 7697.17,6492.73 7711.46,6452.79 7729.59,6414.45 7751.4,6378.07 7776.66,6344 7805.14,6312.57 7836.57,6284.09 7870.63,6258.82 7907.01,6237.01 7945.35,6218.88 7985.28,6204.59 8026.42,6194.28 8068.37,6188.06 8110.73,6185.98 8554.55,6185.98 8554.55,5938.84 8554.05,5934.46 8552.6,5930.3 8550.25,5926.57 8547.13,5923.45 8543.4,5921.1 8539.24,5919.65 8534.86,5919.16 8292.74,5919.16 8288.36,5918.66 8284.2,5917.2 8280.47,5914.86 8277.35,5911.74 8275,5908.01 8273.55,5903.85 8273.05,5899.47 8273.05,5842.37 8273.55,5837.99 8275,5833.83 8277.35,5830.1 8280.47,5826.98 8284.2,5824.64 8288.36,5823.18 8292.74,5822.69 8584.08,5822.69 8588.46,5822.19 8592.62,5820.74 8596.35,5818.39 8599.46,5815.28 8601.81,5811.54 8603.27,5807.38 8603.76,5803 8603.76,4404.41 8603.27,4400.03 8601.81,4395.87 8599.46,4392.13 8596.35,4389.02 8592.62,4386.67 8588.46,4385.21 8584.08,4384.72 8292.74,4384.72 8288.36,4384.23 8284.2,4382.77 8280.47,4380.43 8277.35,4377.31 8275,4373.58 8273.55,4369.41 8273.05,4365.03 8273.05,4307.94 8273.55,4303.56 8275,4299.4 8277.35,4295.67 8280.47,4292.55 8284.2,4290.2 8288.36,4288.75 8292.74,4288.25 8584.08,4288.25 8588.46,4287.76 8592.62,4286.3 8596.35,4283.96 8599.46,4280.84 8601.81,4277.11 8603.27,4272.95 8603.76,4268.57 8603.76,3870.29 8603.27,3865.91 8601.81,3861.75 8599.46,3858.02 8596.35,3854.9 8592.62,3852.55 8588.46,3851.1 8584.08,3850.6 8296.67,3850.6 8288.9,3849.79 8281.46,3847.37 8274.69,3843.46 8268.88,3838.23 8264.28,3831.9 8261.1,3824.76 8259.48,3817.11 8259.48,3809.29 8261.1,3801.64 8264.28,3794.49 8268.88,3788.17 8274.69,3782.93 8281.46,3779.03 8288.9,3776.61 8296.67,3775.79 8584.08,3775.79 8588.46,3775.3 8592.62,3773.84 8596.35,3771.5 8599.46,3768.38 8601.81,3764.64 8603.27,3760.48 8603.76,3756.1 8603.76,2295.89 8603.27,2291.51 8601.81,2287.35 8599.46,2283.62 8596.35,2280.5 8592.62,2278.15 8588.46,2276.7 8584.08,2276.2 8292.74,2276.2 8288.36,2275.71 8284.2,2274.25 8280.47,2271.91 8277.35,2268.79 8275,2265.06 8273.55,2260.9 8273.05,2256.52 8273.05,2199.42 8273.55,2195.04 8275,2190.88 8277.35,2187.15 8280.47,2184.03 8284.2,2181.68 8288.36,2180.23 8292.74,2179.74 8534.86,2179.74 8539.24,2179.24 8543.4,2177.79 8547.13,2175.44 8550.25,2172.32 8552.6,2168.59 8554.05,2164.43 8554.55,2160.05 8554.55,1441.32 8111.63,1441.32 8069.19,1439.23 8027.15,1433 7985.92,1422.67 7945.91,1408.35 7907.49,1390.18 7871.03,1368.33 7836.9,1343.01 7805.41,1314.46 7776.87,1282.97 7751.55,1248.83 7729.7,1212.37 7711.53,1173.95 7697.21,1133.93 7686.89,1092.7 7680.65,1050.65 7678.56,1008.2 7678.56,63.2 7580.14,63.2 7571.38,62.22 7563.06,59.31 7555.59,54.61 7549.36,48.38 7544.67,40.91 7541.76,32.59 7540.77,23.83 7540.77,-15.55 139.19,-15.55 139.19,23.83 138.21,32.59 135.29,40.91 130.6,48.38 124.37,54.61 116.9,59.3 108.58,62.22 99.82,63.2 1.4,63.2 1.4,1008.2 -0.69,1050.65 -6.92,1092.7 -17.25,1133.93 -31.57,1173.95 -49.74,1212.37 -71.59,1248.83 -96.9,1282.97 -125.45,1314.46 -156.94,1343.01 -191.07,1368.33 -227.52,1390.18 -265.94,1408.35 -305.96,1422.67 -347.19,1433 -389.22,1439.23 -431.67,1441.32 -874.59,1441.32 -874.59,2160.05 -874.09,2164.43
